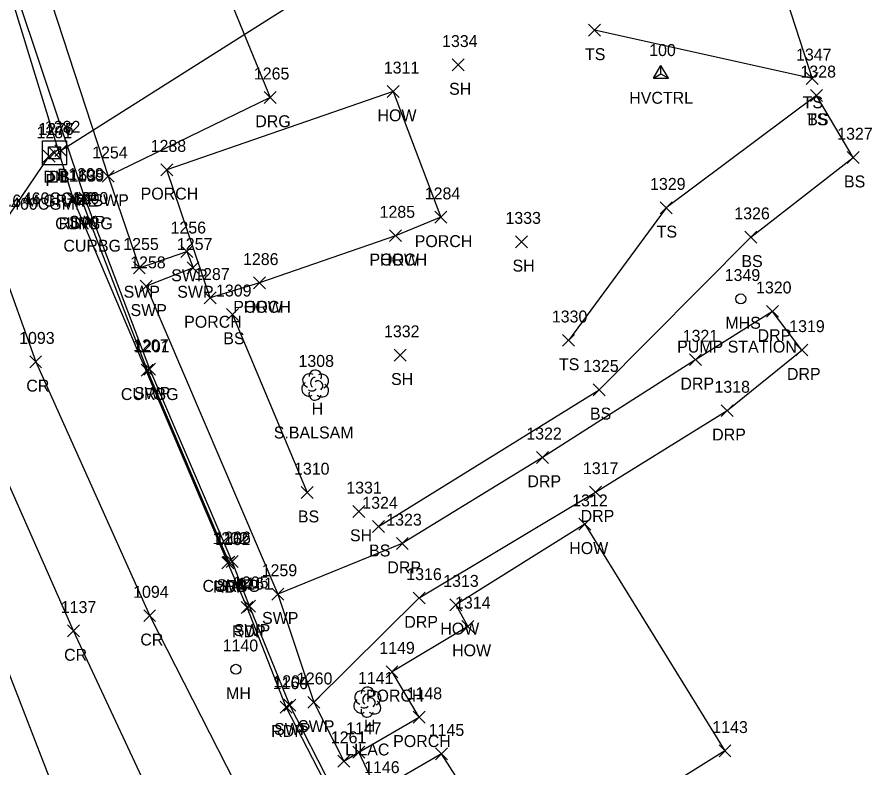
# Model space of a CAD drawing. Extents: x 462930 to 463548, y 29607 to 30453.
# Drawn here: x 463353.81 to 463397.48, y 29966.42 to 30004.79 of the extents above; entities that cross this region are included whole.
import ezdxf

# ---------------------------------------------------------------- set-up
doc = ezdxf.new("R2010")
doc.units = 0
for name, color, linetype in [('C_A', 7, 'Continuous'), ('C_I', 7, 'Continuous'), ('CPSM', 7, 'Continuous'), ('D_A', 7, 'Continuous'), ('D_C', 7, 'Continuous'), ('D_I', 7, 'Continuous'), ('D_TIC', 7, 'Continuous'), ('DCP', 7, 'Continuous'), ('DS', 7, 'Continuous'), ('L_A', 7, 'Continuous'), ('L_C', 7, 'Continuous'), ('L_I', 7, 'Continuous'), ('L_TIC', 7, 'Continuous'), ('LBC', 7, 'Continuous'), ('LBF', 7, 'Continuous'), ('LELB', 7, 'Continuous'), ('LTD', 7, 'Continuous'), ('P_A', 7, 'Continuous'), ('P_I', 7, 'Continuous'), ('P_TIC', 7, 'Continuous'), ('PET', 7, 'Continuous'), ('PRC', 7, 'Continuous'), ('R_A', 7, 'Continuous'), ('R_I', 7, 'Continuous'), ('R_TIC', 7, 'Continuous'), ('RC', 7, 'Continuous'), ('RDG', 7, 'Continuous'), ('RDP', 7, 'Continuous'), ('RSW', 7, 'Continuous'), ('U_A', 7, 'Continuous'), ('U_C', 7, 'Continuous'), ('U_I', 7, 'Continuous'), ('USMH', 7, 'Continuous'), ('UUMH', 7, 'Continuous')]:
    doc.layers.add(name, color=color, linetype=linetype)

msp = doc.modelspace()

# ---------------------------------------------------------------- linework, layer by layer
at = {"layer": 'CPSM'}
for p, q in [((463386.317, 30001.666), (463386.698, 30002.326)), ((463387.079, 30001.666), (463386.698, 30002.326)), ((463386.698, 30001.886), (463386.698, 30002.326)), ((463386.317, 30001.666), (463386.698, 30001.886)), ((463386.698, 30001.886), (463386.698, 30001.886)), ((463386.698, 30001.886), (463387.079, 30001.666)), ((463386.317, 30001.666), (463387.079, 30001.666))]:
    msp.add_line(p, q, dxfattribs=at)
at = {"layer": 'D_TIC'}
for points in [[(463355.147, 29997.385), (463355.757, 29997.995)], [(463355.757, 29997.385), (463355.147, 29997.995)], [(463355.418, 29997.547), (463356.028, 29998.157)], [(463356.028, 29997.547), (463355.418, 29998.157)], [(463355.746, 29997.66), (463356.356, 29998.27)], [(463356.356, 29997.66), (463355.746, 29998.27)]]:
    msp.add_lwpolyline(points, dxfattribs=at)
at = {"layer": 'DCP'}
for points in [[(463388.378, 30018.437), (463356.051, 29997.965)], [(463347.972, 29986.675), (463355.452, 29997.69)], [(463357.242, 29961.347), (463347.606, 29986.199)]]:
    msp.add_lwpolyline(points, dxfattribs=at)
at = {"layer": 'DS'}
for p, q in [((463355.114, 29998.462), (463356.333, 29998.462)), ((463355.114, 29997.243), (463355.114, 29998.462)), ((463356.333, 29998.462), (463356.333, 29997.243)), ((463355.419, 29997.548), (463355.419, 29998.157)), ((463355.419, 29998.157), (463356.028, 29998.157)), ((463356.028, 29998.157), (463356.028, 29997.548)), ((463356.028, 29997.548), (463355.419, 29997.548)), ((463355.725, 29997.853), (463355.725, 29997.853)), ((463355.725, 29997.853), (463355.725, 29997.853)), ((463356.333, 29997.243), (463355.114, 29997.243))]:
    msp.add_line(p, q, dxfattribs=at)
at = {"layer": 'L_TIC'}
for points in [[(463383.001, 30003.812), (463383.611, 30004.422)], [(463383.611, 30003.812), (463383.001, 30004.422)], [(463376.035, 30002.042), (463376.645, 30002.652)], [(463376.645, 30002.042), (463376.035, 30002.652)], [(463394.118, 30001.353), (463394.728, 30001.963)], [(463394.728, 30001.353), (463394.118, 30001.963)], [(463372.714, 30000.686), (463373.324, 30001.296)], [(463373.324, 30000.686), (463372.714, 30001.296)], [(463394.345, 30000.483), (463394.955, 30001.093)], [(463394.955, 30000.483), (463394.345, 30001.093)], [(463394.345, 30000.483), (463394.955, 30001.093)], [(463394.955, 30000.483), (463394.345, 30001.093)], [(463396.221, 29997.306), (463396.831, 29997.916)], [(463396.831, 29997.306), (463396.221, 29997.916)], [(463361.151, 29996.686), (463361.761, 29997.296)], [(463361.761, 29996.686), (463361.151, 29997.296)], [(463386.663, 29994.743), (463387.273, 29995.353)], [(463387.273, 29994.743), (463386.663, 29995.353)], [(463375.152, 29994.256), (463375.762, 29994.866)], [(463375.762, 29994.256), (463375.152, 29994.866)], [(463372.843, 29993.316), (463373.453, 29993.926)], [(463373.453, 29993.316), (463372.843, 29993.926)], [(463372.843, 29993.316), (463373.453, 29993.926)], [(463373.453, 29993.316), (463372.843, 29993.926)], [(463379.274, 29993.005), (463379.884, 29993.615)], [(463379.884, 29993.005), (463379.274, 29993.615)], [(463390.981, 29993.237), (463391.591, 29993.847)], [(463391.591, 29993.237), (463390.981, 29993.847)], [(463365.885, 29990.9), (463366.495, 29991.51)], [(463366.495, 29990.9), (463365.885, 29991.51)], [(463365.885, 29990.9), (463366.495, 29991.51)], [(463366.495, 29990.9), (463365.885, 29991.51)], [(463363.374, 29990.135), (463363.984, 29990.745)], [(463363.984, 29990.135), (463363.374, 29990.745)], [(463364.514, 29989.293), (463365.124, 29989.903)], [(463365.124, 29989.293), (463364.514, 29989.903)], [(463381.669, 29987.967), (463382.279, 29988.577)], [(463382.279, 29987.967), (463381.669, 29988.577)], [(463373.07, 29987.21), (463373.68, 29987.82)], [(463373.68, 29987.21), (463373.07, 29987.82)], [(463383.244, 29985.442), (463383.854, 29986.052)], [(463383.854, 29985.442), (463383.244, 29986.052)], [(463368.325, 29980.189), (463368.935, 29980.799)], [(463368.935, 29980.189), (463368.325, 29980.799)], [(463370.97, 29979.223), (463371.58, 29979.833)], [(463371.58, 29979.223), (463370.97, 29979.833)], [(463382.508, 29978.569), (463383.118, 29979.179)], [(463383.118, 29978.569), (463382.508, 29979.179)], [(463371.961, 29978.448), (463372.571, 29979.058)], [(463372.571, 29978.448), (463371.961, 29979.058)], [(463375.921, 29974.456), (463376.531, 29975.066)], [(463376.531, 29974.456), (463375.921, 29975.066)], [(463376.526, 29973.345), (463377.136, 29973.955)], [(463377.136, 29973.345), (463376.526, 29973.955)], [(463372.658, 29971.033), (463373.268, 29971.643)], [(463373.268, 29971.033), (463372.658, 29971.643)], [(463374.05, 29968.707), (463374.66, 29969.317)], [(463374.66, 29968.707), (463374.05, 29969.317)], [(463370.961, 29966.922), (463371.571, 29967.532)], [(463371.571, 29966.922), (463370.961, 29967.532)], [(463375.181, 29966.839), (463375.791, 29967.449)], [(463375.791, 29966.839), (463375.181, 29967.449)], [(463375.181, 29966.839), (463375.791, 29967.449)], [(463375.791, 29966.839), (463375.181, 29967.449)], [(463389.667, 29966.985), (463390.277, 29967.595)], [(463390.277, 29966.985), (463389.667, 29967.595)]]:
    msp.add_lwpolyline(points, dxfattribs=at)
at = {"layer": 'LBC'}
for points in [[(463373.019, 30000.991), (463361.456, 29996.991)], [(463373.019, 30000.991), (463375.457, 29994.561)], [(463373.148, 29993.621), (463366.19, 29991.205)], [(463382.813, 29978.874), (463376.226, 29974.761), (463376.831, 29973.65)], [(463382.813, 29978.874), (463389.972, 29967.29)], [(463376.831, 29973.65), (463372.963, 29971.338)], [(463389.972, 29967.29), (463379.566, 29960.795), (463375.486, 29967.144)]]:
    msp.add_lwpolyline(points, dxfattribs=at)
at = {"layer": 'LBF'}
for points in [[(463366.19, 29991.205), (463363.679, 29990.44), (463361.456, 29996.991)], [(463375.457, 29994.561), (463373.148, 29993.621)], [(463375.486, 29967.144), (463372.203, 29965.242), (463371.266, 29967.227), (463374.355, 29969.012), (463372.963, 29971.338)]]:
    msp.add_lwpolyline(points, dxfattribs=at)
at = {"layer": 'LELB'}
for points in [[(463381.009, 30038.511), (463385.77, 30025.698), (463385.892, 30016.967), (463391.831, 30009.649), (463394.423, 30001.658), (463383.306, 30004.117)], [(463372.266, 29978.753), (463383.549, 29985.747), (463391.286, 29993.542), (463396.526, 29997.611), (463394.65, 30000.788)], [(463394.65, 30000.788), (463386.968, 29995.048), (463381.974, 29988.272)], [(463364.819, 29989.598), (463368.63, 29980.494)]]:
    msp.add_lwpolyline(points, dxfattribs=at)
at = {"layer": 'LTD'}
for p, q in [((463369.03, 29986.001), (463369.03, 29986.001)), ((463369.03, 29986.001), (463369.03, 29986.001)), ((463371.699, 29969.802), (463371.699, 29969.802)), ((463371.699, 29969.802), (463371.699, 29969.802))]:
    msp.add_line(p, q, dxfattribs=at)
for centre in [(463369.044, 29986.438), (463371.713, 29970.239)]:
    msp.add_arc(centre, 0.319, 335.5272, 180.9563, dxfattribs=at)
for centre, major_axis, ratio, start_param, end_param in [((463368.789, 29986.204), (0.369, -0.156), 0.895232, 1.570796, 4.712389), ((463369.347, 29986.179), (-0.348, -0.147), 0.949671, 1.570796, 4.712389), ((463368.966, 29986.141), (-0.063, -0.241), 0.645439, 3.141593, 6.283185), ((463369.182, 29985.95), (-0.152, 0.203), 0.989748, 3.141593, 6.283185), ((463368.7, 29985.785), (0.178, -0.317), 0.959034, 3.141593, 6.283185), ((463368.89, 29985.772), (-0.19, -0.025), 0.423636, 0, 3.141593), ((463369.335, 29985.747), (-0.332, 0.241), 0.841452, 1.570796, 4.712389), ((463369.03, 29985.544), (0.081, 0.323), 0.942809, 1.570796, 4.712389), ((463371.458, 29970.005), (0.369, -0.156), 0.895232, 1.570796, 4.712389), ((463371.635, 29969.942), (-0.063, -0.241), 0.645439, 3.141593, 6.283185), ((463371.851, 29969.751), (-0.152, 0.203), 0.989748, 3.141593, 6.283185), ((463372.016, 29969.98), (-0.348, -0.147), 0.949671, 1.570796, 4.712389), ((463371.369, 29969.586), (0.178, -0.317), 0.959034, 3.141593, 6.283185), ((463371.559, 29969.573), (-0.19, -0.025), 0.423636, 0, 3.141593), ((463372.004, 29969.548), (-0.332, 0.241), 0.841452, 1.570796, 4.712389), ((463371.699, 29969.345), (0.081, 0.323), 0.942809, 1.570796, 4.712389)]:
    msp.add_ellipse(centre, major_axis=major_axis, ratio=ratio, start_param=start_param, end_param=end_param, dxfattribs=at)
at = {"layer": 'P_TIC'}
for points in [[(463356.39, 29995.17), (463357, 29995.78)], [(463357, 29995.17), (463356.39, 29995.78)], [(463354.455, 29986.872), (463355.065, 29987.482)], [(463355.065, 29986.872), (463354.455, 29987.482)], [(463364.278, 29976.591), (463364.888, 29977.201)], [(463364.888, 29976.591), (463364.278, 29977.201)], [(463365.251, 29974.32), (463365.861, 29974.93)], [(463365.861, 29974.32), (463365.251, 29974.93)], [(463360.279, 29973.897), (463360.889, 29974.507)], [(463360.889, 29973.897), (463360.279, 29974.507)], [(463356.384, 29973.117), (463356.994, 29973.727)], [(463356.994, 29973.117), (463356.384, 29973.727)], [(463367.25, 29969.228), (463367.86, 29969.838)], [(463367.86, 29969.228), (463367.25, 29969.838)]]:
    msp.add_lwpolyline(points, dxfattribs=at)
at = {"layer": 'PET'}
msp.add_lwpolyline([(463374.338, 29956.391), (463367.555, 29969.533), (463365.556, 29974.625), (463364.583, 29976.896), (463356.695, 29995.475), (463352.505, 30009.098), (463350.167, 30017.966), (463347.98, 30027.115), (463347.733, 30028.32), (463346.051, 30037.294), (463343.907, 30048.483), (463342.761, 30054.643), (463342.551, 30055.85), (463341.301, 30062.483), (463338.432, 30077.399), (463338.227, 30078.623), (463337.48, 30086.968), (463337.479, 30088.196), (463338.474, 30099.226), (463339.751, 30104.374), (463341.961, 30110.783)], dxfattribs=at)
at = {"layer": 'PRC'}
for points in [[(463337.978, 30112.385), (463335.087, 30099.771), (463333.576, 30084.385), (463334.686, 30068.796), (463337.03, 30053.748), (463339.908, 30038.01), (463343.632, 30023.045), (463346.617, 30012.904), (463351.044, 29997.524), (463354.76, 29987.177), (463360.584, 29974.202), (463367.548, 29960.534), (463374.695, 29948.349)], [(463361.503, 29963.111), (463356.689, 29973.422), (463352.514, 29982.851), (463349.93, 29989.203)]]:
    msp.add_lwpolyline(points, dxfattribs=at)
at = {"layer": 'R_TIC'}
for points in [[(463366.437, 30000.384), (463367.047, 30000.994)], [(463367.047, 30000.384), (463366.437, 30000.994)], [(463358.161, 29996.349), (463358.771, 29996.959)], [(463358.771, 29996.349), (463358.161, 29996.959)], [(463356.794, 29995.164), (463357.404, 29995.774)], [(463357.404, 29995.164), (463356.794, 29995.774)], [(463356.961, 29995.243), (463357.571, 29995.853)], [(463357.571, 29995.243), (463356.961, 29995.853)], [(463357.216, 29994.024), (463357.826, 29994.634)], [(463357.826, 29994.024), (463357.216, 29994.634)], [(463362.183, 29992.511), (463362.793, 29993.121)], [(463362.793, 29992.511), (463362.183, 29993.121)], [(463359.751, 29991.672), (463360.361, 29992.282)], [(463360.361, 29991.672), (463359.751, 29992.282)], [(463362.492, 29991.67), (463363.102, 29992.28)], [(463363.102, 29991.67), (463362.492, 29992.28)], [(463360.105, 29990.733), (463360.715, 29991.343)], [(463360.715, 29990.733), (463360.105, 29991.343)], [(463392.1, 29989.45), (463392.71, 29990.06)], [(463392.71, 29989.45), (463392.1, 29990.06)], [(463393.6, 29987.473), (463394.21, 29988.083)], [(463394.21, 29987.473), (463393.6, 29988.083)], [(463388.155, 29986.979), (463388.765, 29987.589)], [(463388.765, 29986.979), (463388.155, 29987.589)], [(463360.154, 29986.441), (463360.764, 29987.051)], [(463360.764, 29986.441), (463360.154, 29987.051)], [(463360.279, 29986.493), (463360.889, 29987.103)], [(463360.889, 29986.493), (463360.279, 29987.103)], [(463389.778, 29984.374), (463390.388, 29984.984)], [(463390.388, 29984.374), (463389.778, 29984.984)], [(463380.34, 29981.986), (463380.95, 29982.596)], [(463380.95, 29981.986), (463380.34, 29982.596)], [(463383.059, 29980.216), (463383.669, 29980.826)], [(463383.669, 29980.216), (463383.059, 29980.826)], [(463373.185, 29977.586), (463373.795, 29978.196)], [(463373.795, 29977.586), (463373.185, 29978.196)], [(463364.326, 29976.639), (463364.936, 29977.249)], [(463364.936, 29976.639), (463364.326, 29977.249)], [(463364.496, 29976.67), (463365.106, 29977.28)], [(463365.106, 29976.67), (463364.496, 29977.28)], [(463366.823, 29975.001), (463367.433, 29975.611)], [(463367.433, 29975.001), (463366.823, 29975.611)], [(463374.052, 29974.801), (463374.662, 29975.411)], [(463374.662, 29974.801), (463374.052, 29975.411)], [(463365.384, 29974.379), (463365.994, 29974.989)], [(463365.994, 29974.379), (463365.384, 29974.989)], [(463368.662, 29969.47), (463369.272, 29970.08)], [(463369.272, 29969.47), (463368.662, 29970.08)], [(463367.44, 29969.326), (463368.05, 29969.936)], [(463368.05, 29969.326), (463367.44, 29969.936)], [(463370.194, 29966.461), (463370.804, 29967.071)], [(463370.804, 29966.461), (463370.194, 29967.071)]]:
    msp.add_lwpolyline(points, dxfattribs=at)
at = {"layer": 'RC'}
msp.add_lwpolyline([(463357.099, 29995.469), (463357.521, 29994.329), (463360.459, 29986.746), (463364.631, 29976.944)], dxfattribs=at)
at = {"layer": 'RDG'}
for points in [[(463362.287, 30011.519), (463366.742, 30000.689)], [(463366.742, 30000.689), (463358.466, 29996.654)]]:
    msp.add_lwpolyline(points, dxfattribs=at)
at = {"layer": 'RDP'}
for points in [[(463374.357, 29975.106), (463383.364, 29980.521), (463390.083, 29984.679), (463393.905, 29987.778), (463392.405, 29989.755), (463388.46, 29987.284), (463380.645, 29982.291), (463373.49, 29977.891)], [(463373.49, 29977.891), (463367.128, 29975.306)], [(463374.357, 29975.106), (463368.967, 29969.775)]]:
    msp.add_lwpolyline(points, dxfattribs=at)
at = {"layer": 'RSW'}
for points in [[(463374.235, 29956.952), (463367.745, 29969.631), (463365.689, 29974.684), (463364.801, 29976.975), (463360.584, 29986.798), (463357.266, 29995.548), (463352.711, 30009.142), (463350.357, 30017.977), (463347.93, 30028.371), (463346.21, 30037.33), (463344.933, 30043.874), (463342.934, 30054.68), (463342.697, 30055.906), (463341.529, 30062.506)], [(463343.219, 30061.394), (463344.068, 30056.729), (463345.278, 30049.664), (463349.011, 30050.331), (463349.136, 30049.5), (463345.464, 30048.695), (463348.188, 30034.438), (463349.394, 30028.571), (463351.516, 30018.874), (463354.847, 30019.881), (463355.152, 30018.851), (463351.945, 30017.653), (463354.43, 30009.022), (463358.466, 29996.654), (463360.056, 29991.977), (463362.488, 29992.816), (463362.797, 29991.975), (463360.41, 29991.038), (463367.128, 29975.306), (463368.967, 29969.775), (463370.499, 29966.766)], [(463370.499, 29966.766), (463371.266, 29967.227)]]:
    msp.add_lwpolyline(points, dxfattribs=at)
at = {"layer": 'USMH'}
for p, q in [((463390.78, 29990.39), (463390.78, 29990.39)), ((463391.034, 29990.39), (463391.034, 29990.39))]:
    msp.add_line(p, q, dxfattribs=at)
msp.add_circle((463390.78, 29990.39), 0.254, dxfattribs=at)
at = {"layer": 'UUMH'}
for p, q in [((463364.986, 29971.462), (463364.986, 29971.462)), ((463365.24, 29971.462), (463365.24, 29971.462))]:
    msp.add_line(p, q, dxfattribs=at)
msp.add_circle((463364.986, 29971.462), 0.254, dxfattribs=at)

# ---------------------------------------------------------------- texts
at = {"layer": 'C_A'}
msp.add_text('HVCTRL', height=0.6096, dxfattribs=at).set_placement((463385.08, 30000.362))
at = {"layer": 'C_I'}
msp.add_text('100', height=0.6096, dxfattribs=at).set_placement((463386.1, 30002.8))
at = {"layer": 'D_A'}
for s, height, p in [('P', 0.61, (463355.861, 29996.441)), ('DIB', 0.6096, (463355.145, 29996.328)), ('P', 0.61, (463355.262, 29996.166)), ('DI', 0.6096, (463355.437, 29996.329))]:
    msp.add_text(s, height=height, dxfattribs=at).set_placement(p)
at = {"layer": 'D_C'}
for s, p in [('.6x.6 M GRATE', (463352.25, 29995.11)), ('460CGMP', (463354.1, 29995.222)), ('460CGMP', (463353.501, 29994.947))]:
    msp.add_text(s, height=0.6096, dxfattribs=at).set_placement(p)
at = {"layer": 'D_I'}
for s, p in [('1281', (463354.804, 29998.604)), ('1276', (463354.887, 29998.767)), ('1277', (463354.902, 29998.766)), ('1282', (463355.23, 29998.879))]:
    msp.add_text(s, height=0.6096, dxfattribs=at).set_placement(p)
at = {"layer": 'L_A'}
for s, height, p in [('TS', 0.6096, (463382.821, 30002.593)), ('SH', 0.6096, (463375.879, 30000.823)), ('TS', 0.6096, (463393.938, 30000.134)), ('HOW', 0.6096, (463372.222, 29999.467)), ('TS', 0.6096, (463394.165, 29999.264)), ('BS', 0.6096, (463394.175, 29999.264)), ('BS', 0.6096, (463396.051, 29996.087)), ('PORCH', 0.6096, (463360.122, 29995.467)), ('TS', 0.6096, (463386.483, 29993.524)), ('PORCH', 0.6096, (463374.123, 29993.037)), ('PORCH', 0.6096, (463371.814, 29992.097)), ('HOW', 0.6096, (463372.351, 29992.097)), ('SH', 0.6096, (463379.118, 29991.786)), ('BS', 0.6096, (463390.811, 29992.018)), ('PORCH', 0.6096, (463364.856, 29989.681)), ('HOW', 0.6096, (463365.393, 29989.681)), ('PORCH', 0.6096, (463362.345, 29988.916)), ('BS', 0.6096, (463364.344, 29988.074)), ('TS', 0.6096, (463381.489, 29986.748)), ('SH', 0.6096, (463372.914, 29985.991)), ('H', 0.61, (463368.857, 29984.477)), ('BS', 0.6096, (463383.074, 29984.223)), ('BS', 0.6096, (463368.155, 29978.97)), ('SH', 0.6096, (463370.814, 29978.004)), ('BS', 0.6096, (463371.791, 29977.229)), ('HOW', 0.6096, (463382.016, 29977.35)), ('HOW', 0.6096, (463375.429, 29973.237)), ('HOW', 0.6096, (463376.034, 29972.126)), ('PORCH', 0.6096, (463371.629, 29969.814)), ('H', 0.61, (463371.526, 29968.278)), ('PORCH', 0.6096, (463373.021, 29967.488))]:
    msp.add_text(s, height=height, dxfattribs=at).set_placement(p)
at = {"layer": 'L_C'}
for s, p in [('S.BALSAM', (463366.923, 29983.258)), ('LILAC', (463370.564, 29967.059))]:
    msp.add_text(s, height=0.6096, dxfattribs=at).set_placement(p)
at = {"layer": 'L_I'}
for s, p in [('1334', (463375.519, 30003.261)), ('1347', (463393.602, 30002.572)), ('1311', (463372.544, 30001.905)), ('1328', (463393.829, 30001.702)), ('1328', (463393.829, 30001.702)), ('1327', (463395.705, 29998.525)), ('1288', (463360.635, 29997.905)), ('1329', (463386.145, 29995.962)), ('1284', (463374.636, 29995.475)), ('1285', (463372.327, 29994.535)), ('1285', (463372.327, 29994.535)), ('1326', (463390.448, 29994.456)), ('1333', (463378.758, 29994.224)), ('1286', (463365.352, 29992.119)), ('1286', (463365.352, 29992.119)), ('1287', (463362.858, 29991.354)), ('1309', (463363.972, 29990.512)), ('1330', (463381.127, 29989.186)), ('1332', (463372.554, 29988.429)), ('1308', (463368.185, 29986.915)), ('1325', (463382.728, 29986.661)), ('1310', (463367.956, 29981.408)), ('1331', (463370.627, 29980.442)), ('1324', (463371.445, 29979.667)), ('1312', (463382.165, 29979.788)), ('1313', (463375.578, 29975.675)), ('1314', (463376.183, 29974.564)), ('1149', (463372.313, 29972.252)), ('1141', (463371.224, 29970.716)), ('1148', (463373.707, 29969.926)), ('1147', (463370.618, 29968.141)), ('1145', (463374.838, 29968.058)), ('1145', (463374.838, 29968.058)), ('1143', (463389.324, 29968.204)), ('1146', (463371.538, 29966.156))]:
    msp.add_text(s, height=0.6096, dxfattribs=at).set_placement(p)
at = {"layer": 'P_A'}
for s, p in [('RDP', (463355.929, 29993.951)), ('CR', (463354.282, 29985.653)), ('RDP', (463363.817, 29975.372)), ('RDP', (463364.79, 29973.101)), ('CR', (463360.106, 29972.678)), ('CR', (463356.211, 29971.898)), ('RDP', (463366.789, 29968.009))]:
    msp.add_text(s, height=0.6096, dxfattribs=at).set_placement(p)
at = {"layer": 'P_I'}
for s, p in [('1163', (463356.033, 29996.389)), ('1093', (463353.915, 29988.091)), ('1162', (463363.921, 29977.81)), ('1161', (463365.066, 29975.539)), ('1094', (463359.739, 29975.116)), ('1137', (463356.041, 29974.336)), ('1160', (463366.866, 29970.447))]:
    msp.add_text(s, height=0.6096, dxfattribs=at).set_placement(p)
at = {"layer": 'R_A'}
for s, p in [('DRG', (463365.976, 29999.165)), ('SWP', (463357.662, 29995.13)), ('CURBG', (463355.753, 29993.945)), ('SWP', (463356.462, 29994.024)), ('CURBG', (463356.175, 29992.805)), ('SWP', (463361.684, 29991.292)), ('SWP', (463359.252, 29990.453)), ('SWP', (463361.993, 29990.451)), ('SWP', (463359.606, 29989.514)), ('DRP', (463391.639, 29988.231)), ('DRP', (463393.139, 29986.254)), ('DRP', (463387.694, 29985.76)), ('CURBG', (463359.113, 29985.222)), ('SWP', (463359.78, 29985.274)), ('DRP', (463389.317, 29983.155)), ('DRP', (463379.879, 29980.767)), ('DRP', (463382.598, 29978.997)), ('DRP', (463372.724, 29976.367)), ('CURBG', (463363.285, 29975.42)), ('SWP', (463363.997, 29975.451)), ('SWP', (463366.324, 29973.782)), ('DRP', (463373.591, 29973.582)), ('SWP', (463364.885, 29973.16)), ('SWP', (463366.941, 29968.107)), ('SWP', (463368.163, 29968.251))]:
    msp.add_text(s, height=0.6096, dxfattribs=at).set_placement(p)
at = {"layer": 'R_I'}
for s, p in [('1265', (463365.907, 30001.603)), ('1254', (463357.645, 29997.568)), ('1208', (463356.421, 29996.462)), ('1199', (463356.449, 29996.383)), ('1200', (463356.65, 29995.243)), ('1256', (463361.65, 29993.73)), ('1255', (463359.235, 29992.891)), ('1257', (463361.976, 29992.889)), ('1258', (463359.589, 29991.952)), ('1320', (463391.558, 29990.669)), ('1319', (463393.255, 29988.692)), ('1321', (463387.812, 29988.198)), ('1207', (463359.739, 29987.712)), ('1201', (463359.787, 29987.66)), ('1318', (463389.435, 29985.593)), ('1322', (463379.824, 29983.205)), ('1317', (463382.716, 29981.435)), ('1323', (463372.669, 29978.805)), ('1202', (463363.786, 29977.858)), ('1206', (463363.939, 29977.889)), ('1259', (463366.305, 29976.22)), ('1316', (463373.692, 29976.02)), ('1205', (463364.844, 29975.598)), ('1260', (463368.105, 29970.689)), ('1204', (463366.9, 29970.545)), ('1261', (463369.837, 29967.68))]:
    msp.add_text(s, height=0.6096, dxfattribs=at).set_placement(p)
at = {"layer": 'U_A'}
for s, p in [('MHS', (463389.993, 29988.866)), ('MH', (463364.487, 29969.938))]:
    msp.add_text(s, height=0.6096, dxfattribs=at).set_placement(p)
at = {"layer": 'U_C'}
msp.add_text('PUMP STATION', height=0.6096, dxfattribs=at).set_placement((463387.528, 29987.647))
at = {"layer": 'U_I'}
for s, p in [('1349', (463389.957, 29991.304)), ('1140', (463364.312, 29972.376))]:
    msp.add_text(s, height=0.6096, dxfattribs=at).set_placement(p)

doc.saveas('drawing.dxf')
